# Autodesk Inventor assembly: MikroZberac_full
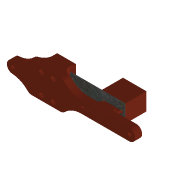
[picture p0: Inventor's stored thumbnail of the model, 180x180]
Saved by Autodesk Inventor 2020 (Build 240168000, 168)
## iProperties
Created: 2022-05
Part Number: MikroZberac_full
Document SubType Name: Assembly
Designer: marti
Author: marti
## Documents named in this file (12)
- D:\VUT FSI Mechatronika\Magisterské\Diplomka\2022_DP_Beno\94_Odevzdane_soubory_priloha_ZP\Príloha A\MikroZberac_full.iam
- D:\VUT FSI Mechatronika\Magisterské\Diplomka\2022_DP_Beno\94_Odevzdane_soubory_priloha_ZP\Príloha A\1.Zakladna.ipt
- D:\VUT FSI Mechatronika\Magisterské\Diplomka\2022_DP_Beno\94_Odevzdane_soubory_priloha_ZP\Príloha A\7.Nosnik.ipt
- D:\VUT FSI Mechatronika\Magisterské\Diplomka\2022_DP_Beno\94_Odevzdane_soubory_priloha_ZP\Príloha A\3.KmitajuciRam.ipt
- D:\VUT FSI Mechatronika\Magisterské\Diplomka\2022_DP_Beno\94_Odevzdane_soubory_priloha_ZP\Príloha A\9.OcelovaPodlozka.ipt
- D:\VUT FSI Mechatronika\Magisterské\Diplomka\2022_DP_Beno\94_Odevzdane_soubory_priloha_ZP\Príloha A\8.Magnet.ipt
- D:\VUT FSI Mechatronika\Magisterské\Diplomka\2022_DP_Beno\94_Odevzdane_soubory_priloha_ZP\Príloha A\9.OcelovaPodlozka_MIR.ipt
- D:\VUT FSI Mechatronika\Magisterské\Diplomka\2022_DP_Beno\94_Odevzdane_soubory_priloha_ZP\Príloha A\8.Magnet_MIR.ipt
- D:\VUT FSI Mechatronika\Magisterské\Diplomka\2022_DP_Beno\94_Odevzdane_soubory_priloha_ZP\Príloha A\5.Cievka1.ipt
- D:\VUT FSI Mechatronika\Magisterské\Diplomka\2022_DP_Beno\94_Odevzdane_soubory_priloha_ZP\Príloha A\6.Cievka2.ipt
- D:\VUT FSI Mechatronika\Magisterské\Diplomka\2022_DP_Beno\94_Odevzdane_soubory_priloha_ZP\Príloha A\4.RedukciaCievka.ipt
- D:\VUT FSI Mechatronika\Magisterské\Diplomka\2022_DP_Beno\94_Odevzdane_soubory_priloha_ZP\Príloha A\2.PritlacnaPlatna.ipt
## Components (13 placed, 11 different names)
1. 1.Zakladna:1 — Mate:10, Flush:14, Mate:13, Flush:15, Mate:14, Mate:15
2. 7.Nosnik:1 — Mate:7, Flush:8, Flush:9, Mate:11, Mate:12, Mate:13
3. 3.KmitajuciRam:1 — Mate:2, Mate:3, Flush:3, Flush:4, Mate:5, Mate:6, Flush:7, Mate:7, Flush:8, Flush:9, Mate:16
4. 9.OcelovaPodlozka:1 — Mate:1, Flush:1, Flush:2, Mate:2, Mate:3, Flush:3
5. 9.OcelovaPodlozka_MIR:1 — Flush:5, Flush:6, Mate:4, Mate:5, Mate:6, Flush:7
6. 5.Cievka1:1 — Mate:8, Flush:10, Flush:11, Mate:9, Flush:12, Flush:13, Mate:16
7. 6.Cievka2:2 — Mate:8, Flush:10, Flush:11
8. 4.RedukciaCievka:1 — Mate:9, Flush:12, Flush:13, Mate:10, Flush:14
9. 2.PritlacnaPlatna:1 — Mate:11, Mate:12, Flush:15, Mate:14, Mate:15
10. 8.Magnet:1 — Mate:1, Flush:1, Flush:2
11. 8.Magnet:2
12. 8.Magnet_MIR:1 — Flush:5, Flush:6, Mate:4
13. 8.Magnet_MIR:2
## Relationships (31: Mate 16, Flush 15)
- Mate:1: 9.OcelovaPodlozka:1 ↔ 8.Magnet:1
- Flush:1: 9.OcelovaPodlozka:1 ↔ 8.Magnet:1
- Flush:2: 9.OcelovaPodlozka:1 ↔ 8.Magnet:1
- Mate:2: 3.KmitajuciRam:1 ↔ 9.OcelovaPodlozka:1
- Mate:3: 3.KmitajuciRam:1 ↔ 9.OcelovaPodlozka:1
- Flush:3: 3.KmitajuciRam:1 ↔ 9.OcelovaPodlozka:1
- Flush:4: 3.KmitajuciRam:1
- Flush:5: 9.OcelovaPodlozka_MIR:1 ↔ 8.Magnet_MIR:1
- Flush:6: 9.OcelovaPodlozka_MIR:1 ↔ 8.Magnet_MIR:1
- Mate:4: 9.OcelovaPodlozka_MIR:1 ↔ 8.Magnet_MIR:1
- Mate:5: 3.KmitajuciRam:1 ↔ 9.OcelovaPodlozka_MIR:1
- Mate:6: 3.KmitajuciRam:1 ↔ 9.OcelovaPodlozka_MIR:1
- Flush:7: 3.KmitajuciRam:1 ↔ 9.OcelovaPodlozka_MIR:1
- Mate:7: 7.Nosnik:1 ↔ 3.KmitajuciRam:1
- Flush:8: 7.Nosnik:1 ↔ 3.KmitajuciRam:1
- Flush:9: 7.Nosnik:1 ↔ 3.KmitajuciRam:1
- Mate:8: 5.Cievka1:1 ↔ 6.Cievka2:2
- Flush:10: 5.Cievka1:1 ↔ 6.Cievka2:2
- Flush:11: 5.Cievka1:1 ↔ 6.Cievka2:2
- Mate:9: 5.Cievka1:1 ↔ 4.RedukciaCievka:1
- Flush:12: 5.Cievka1:1 ↔ 4.RedukciaCievka:1
- Flush:13: 5.Cievka1:1 ↔ 4.RedukciaCievka:1
- Mate:10: 1.Zakladna:1 ↔ 4.RedukciaCievka:1
- Flush:14: 1.Zakladna:1 ↔ 4.RedukciaCievka:1
- Mate:11: 7.Nosnik:1 ↔ 2.PritlacnaPlatna:1
- Mate:12: 7.Nosnik:1 ↔ 2.PritlacnaPlatna:1
- Mate:13: 1.Zakladna:1 ↔ 7.Nosnik:1
- Flush:15: 1.Zakladna:1 ↔ 2.PritlacnaPlatna:1
- Mate:14: 1.Zakladna:1 ↔ 2.PritlacnaPlatna:1
- Mate:15: 1.Zakladna:1 ↔ 2.PritlacnaPlatna:1
- Mate:16: 3.KmitajuciRam:1 ↔ 5.Cievka1:1
